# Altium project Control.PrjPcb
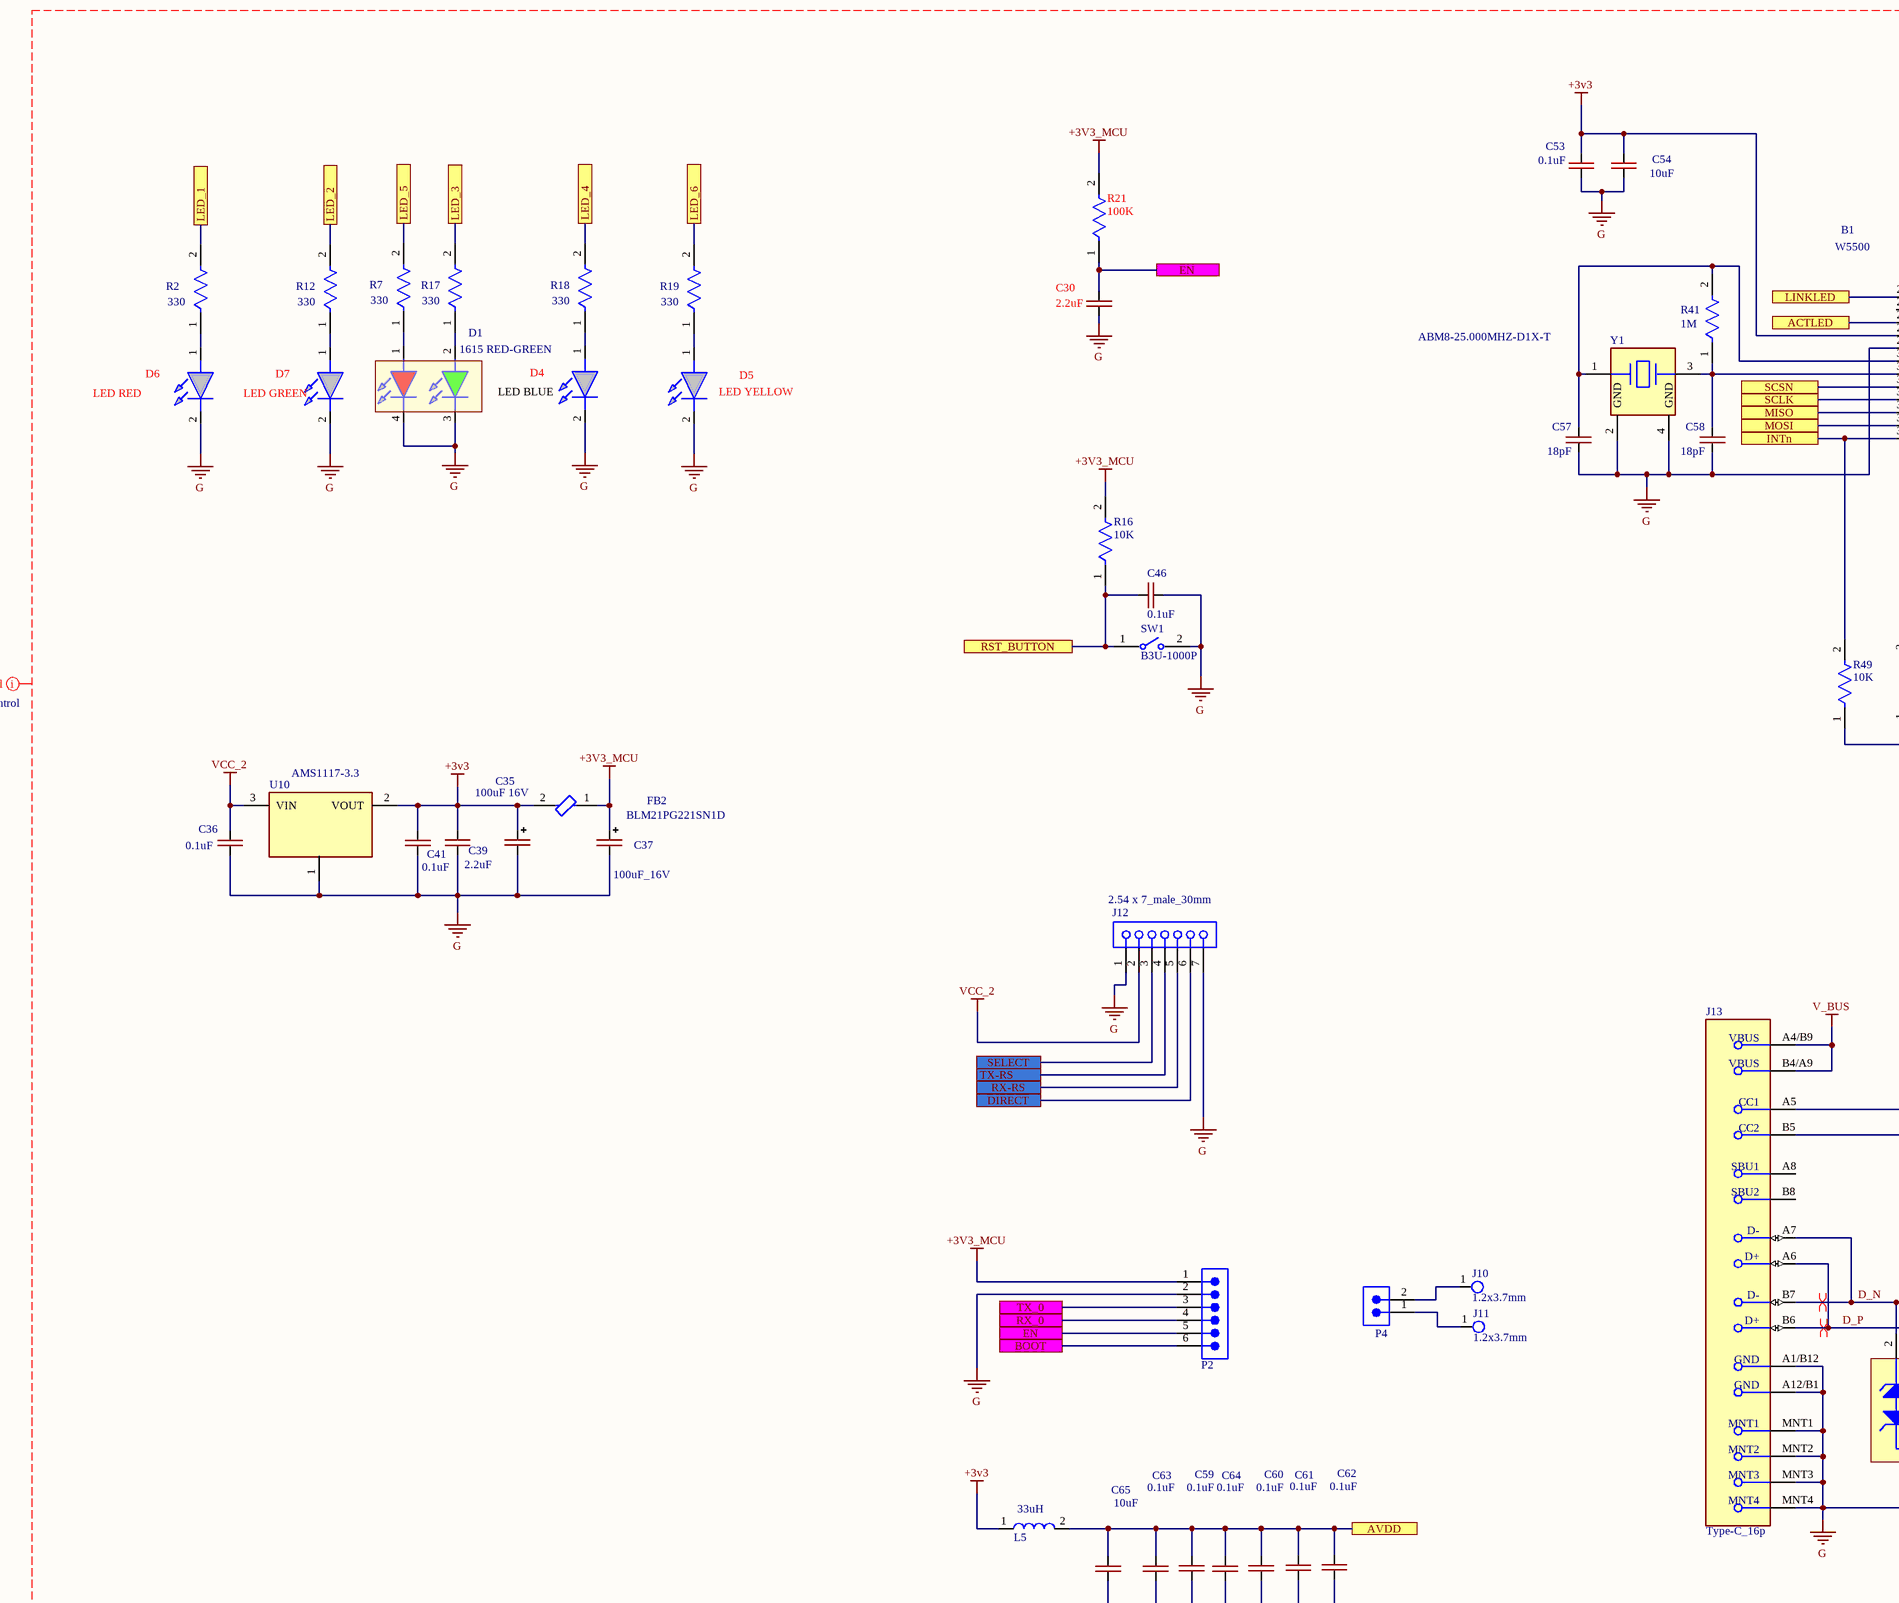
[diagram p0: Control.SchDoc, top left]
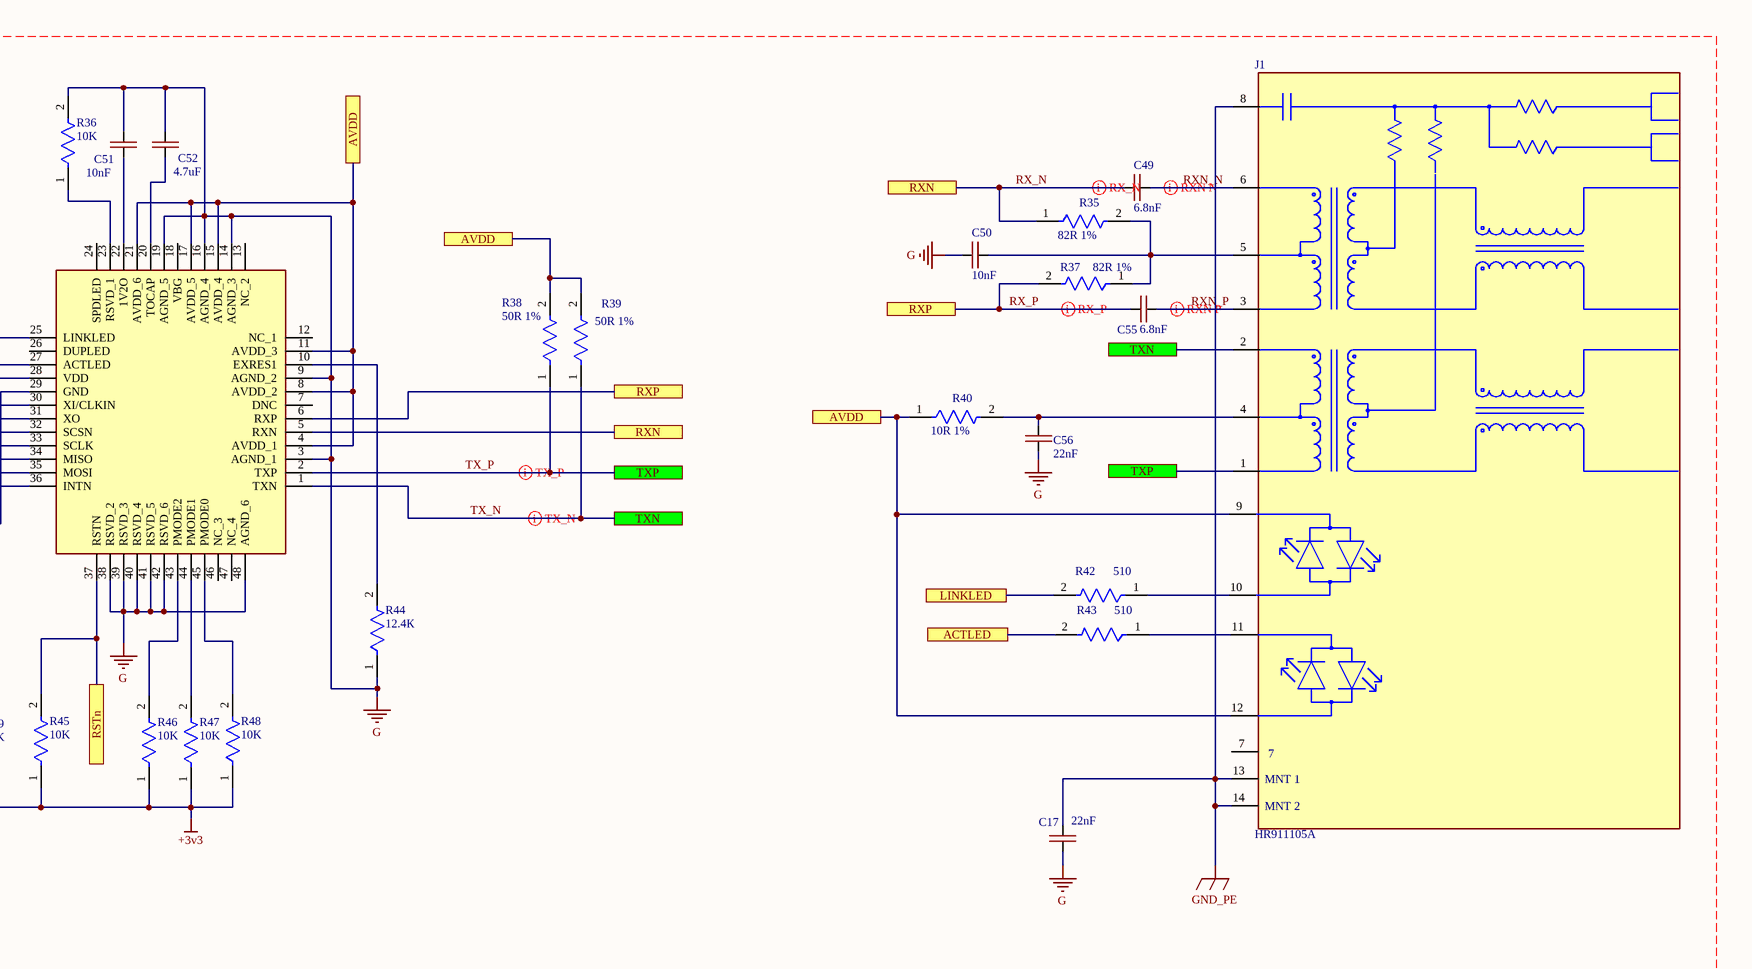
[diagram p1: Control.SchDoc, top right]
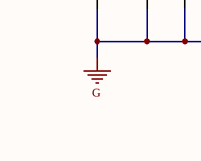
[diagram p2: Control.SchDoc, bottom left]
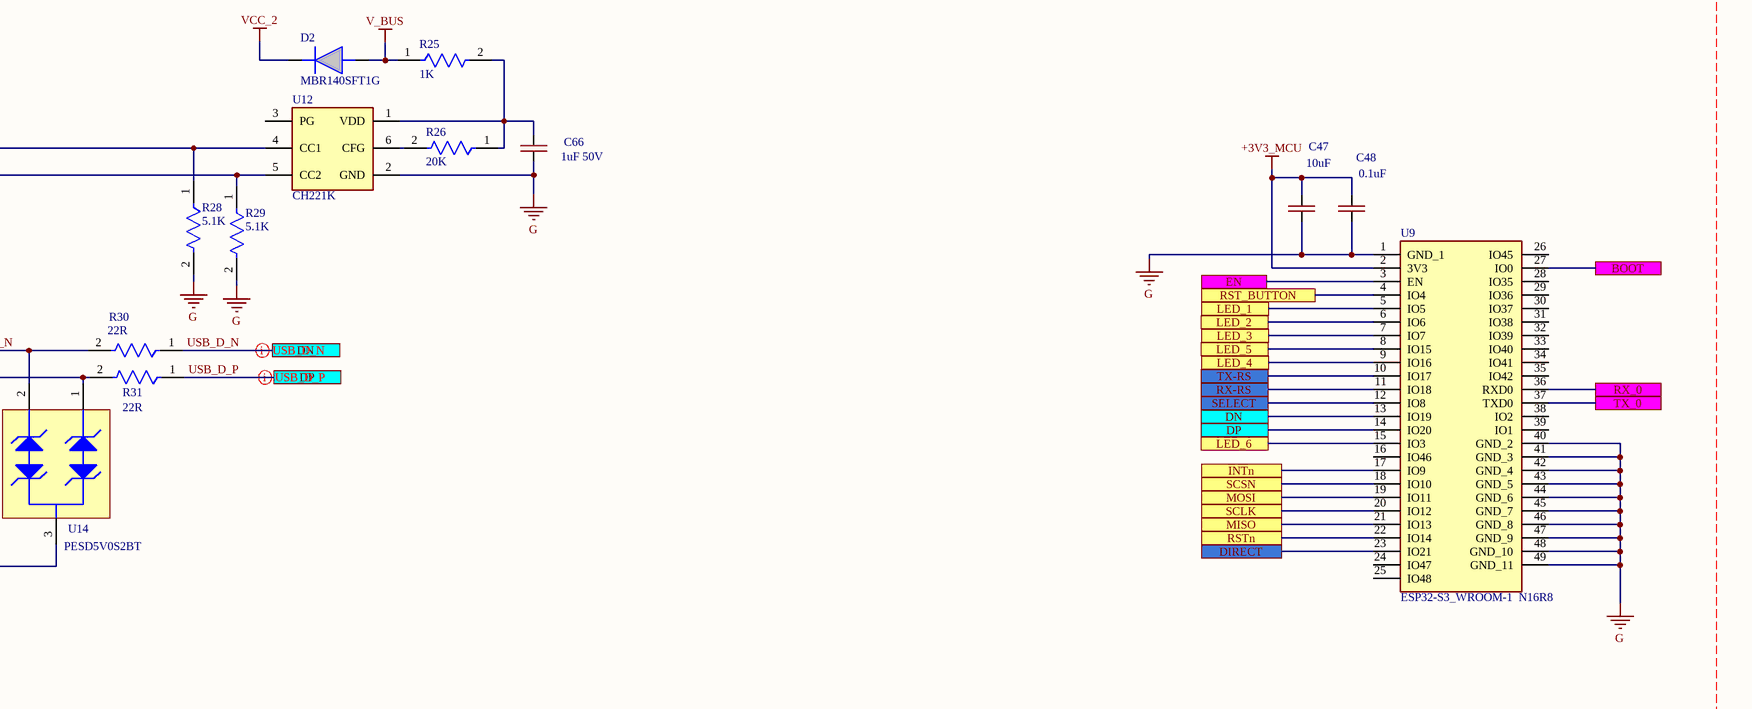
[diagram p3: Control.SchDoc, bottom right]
1 sheet, 79 parts. Net scope: flat (ports and power ports of the same name join across sheets).
Board file: Control.PcbDoc

## Sheet Control.SchDoc
size A1; SheetNumber: 1; SheetTotal: 1; SPICEModelCacheNLVBOJOE: <root> / <DocumentId>NLVBOJOE</DocumentId> / </root>

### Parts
B1  W5500  [QFP50P900X900X160-48N]
C17  22nF  [CAP-0603]
C30  2.2uF  [CAP-0603]
C35  100uF 16V  [CAP-TAN-C]
C36  0.1uF  [CAP-0603]
C37  100uF_16V  [CAP-TAN-C]
C39  2.2uF  [CAP-0603]
C41  0.1uF  [CAP-0603]
C46  0.1uF  [CAP-0603]
C47  10uF  [CAP-0805]
C48  0.1uF  [CAP-0805]
C49  6.8nF  [CAP-0402]
C50  10nF  [CAP-0402]
C51  10nF  [CAP-0603]
C52  4.7uF  [CAP-0603]
C53  0.1uF  [CAP-0603]
C54  10uF  [CAP-0805]
C55  6.8nF  [CAP-0402]
C56  22nF  [CAP-0402]
C57  18pF  [CAP-0402]
C58  18pF  [CAP-0402]
C59  0.1uF  [CAP-0603]
C60  0.1uF  [CAP-0603]
C61  0.1uF  [CAP-0603]
C62  0.1uF  [CAP-0603]
C63  0.1uF  [CAP-0603]
C64  0.1uF  [CAP-0603]
C65  10uF  [CAP-0603]
C66  1uF 50V  [CAP-0805]
D1  1615 RED-GREEN  [LED_Bicolor_1615]
D2  MBR140SFT1G  [SODFL3616X98N]
D4  LED BLUE  [LED_BLUE]
D5  LED YELLOW  [LED_YELLOW]
D6  LED RED  [LED_RED]
D7  LED GREEN  [LED_GREEN]
FB2  BLM21PG221SN1D  [FP-BLM21-0_2-t0_85-e0_5-IPC_A]
J1  HR911105A  [RJ-45]
J10  1.2x3.7mm  [Pad_conn_1.2x3.7mm]
J11  1.2x3.7mm  [Pad_conn_1.2x3.7mm]
J12  2.54 x 7_male_30mm  [2.54_Connector_x7_male_30mm]
J13  Type-C_16p  [Type-C 16p vertical]
L5  33uH  [Coil_4.5x4.5_mm]
P2  61300611121  [61300611121]  (value not drawn)
P4  691305540002  [691305540002]  (value not drawn)
R2  330  [RES-0402]
R7  330  [RES-0402]
R12  330  [RES-0402]
R16  10K  [RES-0402]
R17  330  [RES-0402]
R18  330  [RES-0402]
R19  330  [RES-0402]
R21  100K  [RES-0402]
R25  1K  [RES-0402]
R26  20K  [RES-0402]
R28  5.1K  [RES-0402]
R29  5.1K  [RES-0402]
R30  22R  [RES-0402]
R31  22R  [RES-0402]
R35  82R 1%  [RES-0402]
R36  10K  [RES-0603]
R37  82R 1%  [RES-0402]
R38  50R 1%  [RES-0402]
R39  50R 1%  [RES-0402]
R40  10R 1%  [RES-0402]
R41  1M  [RES-0402]
R42  510  [RES-0402]
R43  510  [RES-0402]
R44  12.4К  [RES-0402]
R45  10K  [RES-0603]
R46  10K  [RES-0603]
R47  10K  [RES-0603]
R48  10K  [RES-0603]
R49  10K  [RES-0603]
SW1  B3U-1000P  [FP-B3U-1000P-B-MFG]
U9  ESP32-S3_WROOM-1  N16R8  [ESP32S3WROOM1N16R8]
U10  AMS1117-3.3  [SOT-89]
U12  CH221K  [SOT-23-6]
U14  PESD5V0S2BT  [PRKT-SOT23-3_V]
Y1  ABM8-25.000MHZ-D1X-T  [FP-ABM8]

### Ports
ACTLED, AVDD, BOOT, DIRECT, DN, DP, EN, INTn, LED_1, LED_2, LED_3, LED_4, LED_5, LED_6, LINKLED, MISO, MOSI, RST_BUTTON, RSTn, RX-RS, RX_0, RXN, RXP, SCLK, SCSN, SELECT, TX-RS, TX_0, TXN, TXP

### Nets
+3v3: B1.28(VDD) C35.1(+) C39.2 C41.2 C53.2 C54.2 FB2.2 L5.1 R45.1 R46.1 R47.1 R48.1 R49.1 U10.2(VOUT)
+3V3_MCU: C37.1(+) C47.2 C48.2 FB2.1 P2.1 R16.2 R21.2 U9.2(3V3)
G: B1.3(AGND_1) B1.9(AGND_2) B1.14(AGND_3) B1.16(AGND_4) B1.19(AGND_5) B1.29(GND) B1.38(RSVD_2) B1.39(RSVD_3) B1.40(RSVD_4) B1.41(RSVD_5) B1.42(RSVD_6) B1.48(AGND_6) C17.1 C30.1 C35.2(-) C36.1 C37.2(-) C39.1 C41.1 C46.1 C47.1 C48.1 C50.1 C51.2 C52.2 C53.1 C54.1 C56.1 C57.1 C58.1 C59.1 C60.1 C61.1 C62.1 C63.1 C64.1 C65.1 C66.1 D1.3(K) D1.4(K) D4.2(K) D5.2(K) D6.2(K) D7.2(K) J12.1 J12.7 J13.A1/B12(GND) J13.A12/B1(GND) J13.MNT1 J13.MNT2 J13.MNT3 J13.MNT4 P2.2 R28.2 R29.2 R36.2 R44.1 SW1.2 U9.1(GND_1) U9.40(GND_2) U9.41(GND_3) U9.42(GND_4) U9.43(GND_5) U9.44(GND_6) U9.45(GND_7) U9.46(GND_8) U9.47(GND_9) U9.48(GND_10) U9.49(GND_11) U10.1(Ground) U12.2(GND) U14.3 Y1.2(GND) Y1.4(GND)
GND_PE: C17.2 J1.8 J1.13(MNT_1) J1.14(MNT_2)
V_BUS: D2.2(A) J13.A4/B9 J13.B4/A9 R25.1
VCC_2: C36.2 D2.1(K) J12.2 U10.3(VIN)
D_N: J13.A7(D-) J13.B7(D-) R30.2 U14.2
D_P: J13.A6(D+) J13.B6(D+) R31.2 U14.1
RX_N: B1.5(RXN) C49.2 R35.1 ; port RXN
RX_P: B1.6(RXP) C55.2 R37.2 ; port RXP
RXN_N: C49.1 J1.6
RXN_P: C55.1 J1.3
TX_N: B1.1(TXN) J1.2 R39.1 ; port TXN
TX_P: B1.2(TXP) J1.1 R38.1 ; port TXP
USB_D_N: R30.1 U9.13(IO19) ; port DN
USB_D_P: R31.1 U9.14(IO20) ; port DP
NetB1_4: B1.4(AVDD_1) B1.8(AVDD_2) B1.11(AVDD_3) B1.15(AVDD_4) B1.17(AVDD_5) B1.21(AVDD_6) C59.2 C60.2 C61.2 C62.2 C63.2 C64.2 C65.2 J1.9(2_ANODE_YELLOW/CATHODE_GREEN) J1.12(2_CATHODE_YELLOW/ANODE_GREEN) L5.2 R38.2 R39.2 R40.1 ; port AVDD
NetB1_10: B1.10(EXRES1) R44.2
NetB1_20: B1.20(TOCAP) C52.1
NetB1_22: B1.22(1V2O) C51.1
NetB1_23: B1.23(RSVD_1) R36.1
NetB1_25: B1.25(LINKLED) R42.2 ; port LINKLED
NetB1_27: B1.27(ACTLED) R43.2 ; port ACTLED
NetB1_30: B1.30(XI/CLKIN) C57.2 R41.2 Y1.1
NetB1_31: B1.31(XO) C58.2 R41.1 Y1.3
NetB1_32: B1.32(SCSN) U9.18(IO10) ; port SCSN
NetB1_33: B1.33(SCLK) U9.20(IO12) ; port SCLK
NetB1_34: B1.34(MISO) U9.21(IO13) ; port MISO
NetB1_35: B1.35(MOSI) U9.19(IO11) ; port MOSI
NetB1_36: B1.36(INTN) R49.2 U9.17(IO9) ; port INTn
NetB1_37: B1.37(RSTN) R45.2 U9.22(IO14) ; port RSTn
NetB1_43: B1.43(PMODE2) R46.2
NetB1_44: B1.44(PMODE1) R47.2
NetB1_45: B1.45(PMODE0) R48.2
NetC30_2: C30.2 P2.5 R21.1 U9.3(EN) ; port EN
NetC46_2: C46.2 R16.1 SW1.1 U9.4(IO4) ; port RST_BUTTON
NetC50_2: C50.2 J1.5 R35.2 R37.1
NetC56_2: C56.2 J1.4 R40.2
NetC66_2: C66.2 R25.2 R26.1 U12.1(VDD)
NetD1_1: D1.1(A) R7.1
NetD1_2: D1.2(A) R17.1
NetD4_1: D4.1(A) R18.1
NetD5_1: D5.1(A) R19.1
NetD6_1: D6.1(A) R2.1
NetD7_1: D7.1(A) R12.1
NetJ1_10: J1.10(2_CATHODE_YELLOW/ANODE_GREEN) R42.1
NetJ1_11: J1.11(2_ANODE_YELLOW/CATHODE_GREEN) R43.1
NetJ10_1: J10.1 P4.2
NetJ11_1: J11.1 P4.1
NetJ12_3: J12.3 U9.12(IO8) ; port SELECT
NetJ12_4: J12.4 U9.10(IO17) ; port TX-RS
NetJ12_5: J12.5 U9.11(IO18) ; port RX-RS
NetJ12_6: J12.6 U9.23(IO21) ; port DIRECT
NetJ13_A5: J13.A5 R28.1 U12.4(CC1)
NetJ13_B5: J13.B5 R29.1 U12.5(CC2)
NetP2_3: P2.3 U9.37(TXD0) ; port TX_0
NetP2_4: P2.4 U9.36(RXD0) ; port RX_0
NetP2_6: P2.6 U9.27(IO0) ; port BOOT
NetR2_2: R2.2 U9.5(IO5) ; port LED_1
NetR7_2: R7.2 U9.8(IO15) ; port LED_5
NetR12_2: R12.2 U9.6(IO6) ; port LED_2
NetR17_2: R17.2 U9.7(IO7) ; port LED_3
NetR18_2: R18.2 U9.9(IO16) ; port LED_4
NetR19_2: R19.2 U9.15(IO3) ; port LED_6
NetR26_2: R26.2 U12.6(CFG)

Not connected (* = marked no-connect by the designer): B1 7(DNC) 12(NC_1) 13(NC_2) 18(VBG) 24(SPDLED) 26(DUPLED) 46(NC_3) 47(NC_4); J1 7; J13 A8 B8; U9 16(IO46) 24(IO47) 25(IO48) 26(IO45) 28(IO35) 29(IO36) 30(IO37) 31(IO38) 32(IO39) 33(IO40) 34(IO41) 35(IO42) 38(IO2) 39(IO1); U12 3(PG)

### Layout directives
differential pair: D_N, D_P, RX_N, RX_P, RXN_N, RXN_P, TX_N, TX_P, USB_D_N, USB_D_P
CompClassName: Control: +3v3, +3V3_MCU, D_N, D_P, G, GND_PE, RX_N, RX_P, RXN_N, RXN_P, TX_N, TX_P, USB_D_N, USB_D_P, V_BUS, VCC_2

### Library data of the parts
B1 = W5500: Ethernet ICs 3in1 Enet Controller TCP/IP +MAC+PHY; Manufacturer_Name: Wiznet Technology; Geometry.Height: 1.6mm
C17 C30 C39 C41 C46-C66 = CAP-NON-POLAR
C35 = CAP-POLAR: 100uF_16V  size-C / Kyocera AVX / TAJC107K016RNJ
C36 = CAP-NON-POLAR: 0.1uF 16V
C37 = CAP_POL_SMD: 100uF_16V  size-C / Kyocera AVX / TAJC107K016RNJ
D1 = LED Bicolor: 1615 bicolor SMD LED 2 colors Red+GREEN / DY-S161506URUGC-T10-4T-03
D2 = MBR140SFT1G: MBR140SFT1G / DIODE SCHOTTKY 40V 1A SOD123L
D4 = LED: XL-2012UBC XINGLIGHT 0805 LED BLUE; Manufacturer_Name: Wurth Elektronik; Manufacturer_Part_Number: 151031YS06000; Geometry.Height: 5.5mm
D5 = LED: XL-2012UYC  XINGLIGHT 0805 LED YELLOW; Manufacturer_Name: Wurth Elektronik; Manufacturer_Part_Number: 151031YS06000; Geometry.Height: 5.5mm
D6 = LED: XL-2012SURC   XINGLIGHT  0805  LED RED; Manufacturer_Name: Wurth Elektronik; Manufacturer_Part_Number: 151031YS06000; Geometry.Height: 5.5mm
D7 = LED: XL-2012SYGC-06  XINGLIGHT  0805  LED GREEN; Manufacturer_Name: Wurth Elektronik; Manufacturer_Part_Number: 151031YS06000; Geometry.Height: 5.5mm
FB2 = BLM21PG221SN1D: Chip Ferrite Bead, 0805, 220Ω @ 100MHz, 0.045Ω, 25%, 2A
J1 = HRK1-1B72F09
J10 J11 = Klema_15_A
J12 = 2.54_Connector_x7_male_25mm: 2.54_Connector_x7_male_30mm / Pitch Single Row Male Header Needle Height Long 30mm
J13 = Type-C_16p: Type-C_16p  TYPE-C16P female socket vertical plug-in patch 8.8 mm / TYPE-C-31-D-16 / https://www.aliexpress.com/item/1005012731556882.html?spm=a2g0o.cart.0.0.a5d038da7FoSd6&mp=1&pdp_npi=6%40dis%21UAH%21UAH+257.01%21UAH+231.29%21%21UAH+223.44%21%21%21%402103842a17955063158303339e1049%2112000059158355455%21ct%21UA%214339914066%21%211%210%21
L5 = Coil
P2 = 61300611121: WR-PHD Pin Header, THT, Vertical, pitch 2.54mm, 1 Row, 6P; Manufacturer: Wurth Elektronik; Contact Resistance: 20mΩ; Rated Current: 3A; Working Voltage: 250V; Withstanding Voltage: 500V
P4 = 691305540002: WR-TBL Series 3055 PCB Header Horizontal Entry with Plastic Latches, THT, pitch 5.08mm, 02p; Manufacturer: Wurth Elektronik; Modularity: No; Rated Current: 16A; Working Voltage: 300V (AC)
R2 R7 R12 R16-R19 R21 R25 R26 R28-R31 R35-R43 R45-R49 = RES-CONST
R44 = RES-CONST: 12.4К  1%
U9 = ESP32-S3_WROOM-1 N16R8
U10 = AMS1117
U12 = CH221K: WCH CH221K / https://www.lcsc.com/product-detail/C5125736.html?s_z=n_q_x_CH221K&spm=wm.ssy.em.0.tz&lcsc_vid=T1ILBVxSEgBWUlIFElIIVl1eEgJYAVZUQVBaAlBUQVExVlNfQlRfXlNXQ1JfUTsOAxUeFF5JWBYZEEoKFBINSQcJGk4NBhADEA4cHktXRlVeSQwSGg0%3D
U14 = CMP-2000-07553-1: TVS Array - Low capacitance bidirectional double ESD protection diode / https://www.lcsc.com/product-detail/C49338.html?s_z=n_q_PESD5V0S2BT&spm=wm.fly.bg.0.xh&lcsc_vid=T1ILBVxSEgBWUlIFElIIVl1eEgJYAVZUQVBaAlBUQVExVlNfQldfUFRWQVRbVDsOAxUeFF5JWBYZEEoKFBINSQcJGk4NBhADEA4cHktRR1NADxALGw%3D%3D; Manufacturer: Protek Devices; Min Breakdown Voltage: 7.5V; Capacitance: 75pF; Current: 20uA; Power Dissipation: 600W; Working Voltage: 7V; Voltage: 12V; Case\/Package: SOT-23; Clamping Voltage: 17V; Element Configuration: Dual
Y1 = ABM8-25.000MHZ: Crystal 25MHz ±10ppm 18pF SMD-4 3.2mm x 2.5mm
